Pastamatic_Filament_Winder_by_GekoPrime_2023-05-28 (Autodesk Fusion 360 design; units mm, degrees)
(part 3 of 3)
sketch "Sketch13" plane through (24.4187, 0, 0) normal (1, 0, 0) x axis (0, 0, -1)
  line L1 (0, 144.049) -> (0, 124.978)
  line L2 (-11.6, 144.049) -> (0, 144.049)
  line L3 (-11.6, 124.978) -> (-11.6, 144.049)
  line L4 (0, 124.978) -> (-11.6, 124.978)
  line L5 (0, 58.3113) -> (-1, 58.3113)
  line L6 (0, 124.978) -> (0, 58.3113)
  line L7 (-1, 124.978) -> (0, 124.978)
  line L8 (-1, 58.3113) -> (-11.6, 58.3113)
  line L9 (-11.6, 58.3113) -> (-11.6, 124.978)
  line L10 (-11.6, 91.6446) -> (0, 91.6446)
  point P9 (0, 124.978)
  point P10 (0, 124.978)
  point P7 (-1, 58.3113)
  point P12 (-1, 58.3113)
  point P5 (-11.6, 124.978)
  point P13 (-11.6, 124.978)
  point P14 (0, 91.6446)
  point P15 (-11.6, 91.6446)
  point P8 (0, 58.3113)
  perpendicular L5 L6
  perpendicular L6 L7
  coincident P9 P10
  collinear L1 L6
  coincident P7 P12
  coincident P5 P13
  perpendicular L8 L9
  midpoint L6 P14
  midpoint L9 P15
  dimension "d1790" distance L4 P8 = 66.6667 (= "spool_od_bambu / 3")
extrude "Extrude74" sketch "Sketch13" profile of L4 L5 L6 L7 L8 to an object
sketch "Sketch14" plane through (0, 58.3113, 0) normal (0, -1, 0) x axis (1, 0, 0)
  line L1 (-24.4187, 0) -> (-24.4187, 11.6)
  line L2 (24.4187, 0) -> (-24.4187, 0)
  line L3 (24.4187, 11.6) -> (24.4187, 0)
  line L4 (-24.4187, 11.6) -> (24.4187, 11.6)
  line L5 (1.6971, 23.0752) -> (0, 11.6)
  line L6 (-0.8578, 5.8) -> (0, 11.6)
  line L7 (1.2328, 23.3532) -> (-1.2825, 6.3455)
  line L8 (2.222, 23.2069) -> (-0.2933, 6.1992)
  line L9 (-1.2825, 6.3455) -> (-0.2933, 6.1992)
  line L10 (2.222, 23.2069) -> (1.2328, 23.3532)
  line L11 (2.2444, 21.9905) -> (1.2328, 23.3532)
  line L12 (1.6353, 8.3557) -> (0.2867, 3.9841)
  line L13 (-0.2217, 3.2655) -> (-2.2002, 3.5581)
  line L14 (0.0407, 3.4603) -> (-0.2217, 3.2655)
  line L15 (-2.1671, 5.3975) -> (-1.7718, 5.6257)
  arc A1 centre (1.8005, 23.7747) radius 0.7071 clockwise from (1.2328, 23.3532) to (2.222, 23.2069)
  arc A2 centre (0.6959, 6.0529) radius 1 clockwise from (-0.0333, 5.3686) to (-0.2933, 6.1992)
  arc A3 centre (1.3684, 10.6) radius 1 clockwise from (0.3792, 10.7463) to (1.3684, 11.6)
  arc A4 centre (-1.6642, 10.6) radius 1 clockwise from (-1.6642, 11.6) to (-0.675, 10.4537)
  arc A5 centre (3.1652, 22.749) radius 1 clockwise from (2.1759, 22.8953) to (2.3658, 23.3498)
  arc A6 centre (0.1974, 23.1879) radius 1 clockwise from (1.1365, 23.5316) to (1.1867, 23.0416)
  arc A7 centre (-1.0647, 4.401) radius 1.4142 clockwise from (-0.0333, 5.3686) to (-1.7718, 5.6257)
  arc A8 centre (-2.2718, 6.4918) radius 1 clockwise from (-1.2825, 6.3455) to (-1.7718, 5.6257)
  point P6 (0, 11.6)
  point P12 (2.222, 23.2069)
  point P14 (2.222, 23.2069)
  point P7 (1.6971, 23.0752)
  point P13 (1.8005, 23.7747)
  point P15 (-0.7879, 6.2723)
  point P29 (2.1759, 22.8953)
  point P28 (2.3658, 23.3498)
  point P31 (1.1867, 23.0416)
  point P32 (1.1365, 23.5316)
  point P23 (0.3792, 10.7463)
  point P22 (1.3684, 11.6)
  point P26 (-1.6642, 11.6)
  point P25 (-0.675, 10.4537)
  point P19 (-0.2933, 6.1992)
  point P33 (-1.0647, 4.401)
  point P11 (-0.2933, 6.1992)
  point P34 (0.2867, 3.9841)
  point P8 (-0.8578, 5.8)
  point P36 (-2.2002, 3.5581)
  point P37 (-0.2217, 3.2655)
  point P9 (-1.2825, 6.3455)
  point P40 (-1.2825, 6.3455)
  point P10 (1.2328, 23.3532)
  midpoint L4 P6
  coincident P12 P14
  coincident P7 A1
  coincident L5 P13
  midpoint L9 P15
  coincident L6 P15
  perpendicular L6 L9
  perpendicular L8 L9
  perpendicular L5 L10
  tangent A1 L11
  coincident L8 P29
  coincident A1 P28
  coincident L7 P31
  coincident A1 P32
  coincident L8 P23
  coincident L4 P22
  coincident L4 P26
  coincident L7 P25
  coincident L8 P19
  tangent L8 A2
  equal A3 A4
  tangent A1 A6
  tangent L8 A5
  tangent A1 A5
  equal A5 A6
  equal A3 A5
  equal A2 A3
  tangent L4 A4
  tangent L7 A4
  tangent L4 A3
  tangent L8 A3
  tangent L7 A6
  coincident L6 P33
  tangent A2 A7
  coincident P11 P19
  coincident A7 P34
  tangent A7 L12
  collinear L5 L6
  coincident P8 A7
  coincident A7 P36
  coincident A7 P37
  tangent A7 L14
  perpendicular L6 L13
  coincident P9 P40
  tangent L7 A8
  tangent A7 A8
  tangent A7 L15
  dimension "d1810" distance L1 L3 = 48.8375
  dimension "d1816" distance P10 P14 = 1
  dimension "d1817" angle L7 L11 = 45
  dimension "d1818" distance P6 P7 = 11.6 (= "stack_unit")
  dimension "d1837" distance L4 P8 = 5.8 (= "stack_unit / 2")
  dimension "d1838" radius A5 = 1 (= "wall_thickness / 2")
  dimension "d1839" angle L6 L14 = 45
  dimension "d1843" distance P36 P37 = 2 (= "wall_thickness")
  dimension "d1844" angle L4 L15 = 30
extrude "Extrude75" cut sketch "Sketch14" profile of L4 L7 L8 A1 A2 A3 A4 A5 A6 A7 L13 A8 against normal blind 66.6667 (magnitude of "-spool_od_bambu / 3")
chamfer "Chamfer19" distance 0.5 (= "wall_thickness / 4")
rectangular_pattern "R-Pattern2" uSpaceDistance 20 (= "( 40 / 2 ) * 1 mm") vSpaceDistance 0
fillet "Fillet23" radius 2 (= "wall_thickness")
mirror "Mirror7" mirrorStitchTolerance 0.1 bodies "wiper_mount_right"
extrude "Extrude76" new body sketch "Sketch14" profile of L4 L7 L8 A1 A2 A7 L13 A8 to an object bodies "wiper_blade_tpu"
sketch "Sketch16" plane through (0, 0, -11.6) normal (0, 0, -1) x axis (-1, 0, 0)
  line L1 (-183.0785, 143.3824) -> (-182.4118, 144.049)
  line L2 (-183.0785, 108.049) -> (-183.0785, 143.3824)
  line L3 (-30.6569, 22.24) -> (-11.98, 40.9168)
  line L4 (-21.6788, -11.5706) -> (-32.3575, 13.4419)
  line L5 (-14, 0) -> (-14, -10)
  line L6 (14, -10) -> (14, 0)
  line L7 (32.3575, 13.4419) -> (21.6788, -11.5706)
  line L8 (18.3848, 118.5932) -> (-1.6205, 98.5879)
  line L9 (24.4187, 144.049) -> (24.4187, 131.5812)
  line L10 (7.0711, 144.049) -> (24.4187, 144.049)
  line L11 (4.1421, 126.978) -> (7.0711, 129.9069)
  line L12 (-4.1421, 126.978) -> (4.1421, 126.978)
  line L13 (-7.0711, 129.9069) -> (-4.1421, 126.978)
  line L14 (-182.4118, 144.049) -> (-7.0711, 144.049)
  curve K1
  curve K2
  curve K3
  curve K4
  arc A1 centre (-175.0785, 108.049) radius 8 clockwise from (-172.1153, 100.618) to (-183.0785, 108.049)
  arc A2 centre (-118.7313, -33.2588) radius 144.1279 clockwise from (-172.1153, 100.618) to (-11.3759, 62.906)
  arc A3 centre (-23.2937, 52.2305) radius 16 clockwise from (-11.3759, 62.906) to (-11.98, 40.9168)
  arc A4 centre (-25, 16.5831) radius 8 clockwise from (-32.3575, 13.4419) to (-30.6569, 22.24)
  arc A5 centre (-18, -10) radius 4 clockwise from (-14, -10) to (-21.6788, -11.5706)
  arc A6 centre (0, 0) radius 14 clockwise from (-14, 0) to (14, 0)
  arc A7 centre (18, -10) radius 4 clockwise from (21.6788, -11.5706) to (14, -10)
  arc A8 centre (25, 16.5831) radius 8 clockwise from (32.5585, 19.2039) to (32.3575, 13.4419)
  arc A9 centre (-118.7313, -33.2588) radius 160.1279 clockwise from (-1.9733, 76.3246) to (32.5585, 19.2039)
  arc A10 centre (9.6932, 87.2742) radius 16 clockwise from (-1.9733, 76.3246) to (-1.6205, 98.5879)
  arc A11 centre (0, 136.978) radius 26 clockwise from (21.8887, 122.9464) to (18.3848, 118.5932)
  arc A12 centre (8.4187, 131.5812) radius 16 clockwise from (24.4187, 131.5812) to (21.8887, 122.9464)
  arc A13 centre (0, 136.978) radius 10 clockwise from (7.0711, 144.049) to (7.0711, 129.9069)
  arc A14 centre (0, 136.978) radius 10 clockwise from (-7.0711, 129.9069) to (-7.0711, 144.049)
  circle C1 centre (25, 16.5831) radius 4.15
  circle C2 centre (7.04, 52.3244) radius 4.15
  circle C3 centre (-25, 16.5831) radius 4.15
  circle C4 centre (-62.3842, 108.049) radius 4.15
  circle C5 centre (-19.6153, 82.1488) radius 4.15
  circle C6 centre (-175.0785, 108.049) radius 4.15
  point P2 (-182.4118, 144.049)
  point P40 (-7.0711, 144.049)
  coincident P2
  coincident P40
  tangent A2 K3
  dimension "d1845" Text1-Height = 20
emboss "Emboss4" sketch "Sketch16" Depth -0.16 Horizontal Distance 0 Vertical Distance 0 Rotation Angle 0
joint_origin "JointOrigin20"
joint_origin "JointOrigin19"
joint_origin "JointOrigin21"
joint_origin "JointOrigin23"
joint_origin "JointOrigin24"
joint_origin "JointOrigin25"
joint_origin "JointOrigin26"
joint_origin "JointOrigin44"
joint_origin "JointOrigin45"
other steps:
base_feature "Base Feature3" bodies "spur_gear_30t_7mm"
base_feature "Base Feature4" bodies "spur_gear_50t_7mm (1)"
base_feature "Base Feature12" bodies "spool_passive", "spool_passive_long"
base_feature "Base Feature11" bodies "spool_active", "spindle_male_passive"
base_feature "Base Feature10" bodies "spur_gear_10t_7mm"
base_feature "紁ऀ" bodies "spur_gear_10t_7mm", "double_idler"
create_component "CreateComponent25"
create_component "CreateComponent37"
create_component "CreateComponent38"
create_component "CreateComponent39"
create_component "CreateComponent40"
create_component "CreateComponent41"
create_component "CreateComponent42"
create_component "CreateComponent43"
create_component "CreateComponent45"
create_component "CreateComponent47"
named bodies: "groove", "leadscrew_tooth", "idler", "spur_gear_40t_7mm", "leadscrew_pin", "spool_active_bolt", "nut_negative", "spindle_male_driven", "nut_positive", "spindle_female", "spur_gear_10t_7mm", "spur_gear_50t_7mm", "spool_cap", "cradle_crossbar", "spur_gear_50t_7mm (1)", "leadscrew_block", "driven_target_cradle", "double_idler", "passive_target_cradle", "source_cradle", "spur_gear_10t_14mm_6mmD", "spur_gear_30t_7mm", "pin_long", "pin_short", "spool_active", "spindle_male_passive", "spool_passive", "spool_passive_long", "leadscrew", "wiper_mount_left", "wiper_mount_right", "wiper_blade_tpu"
